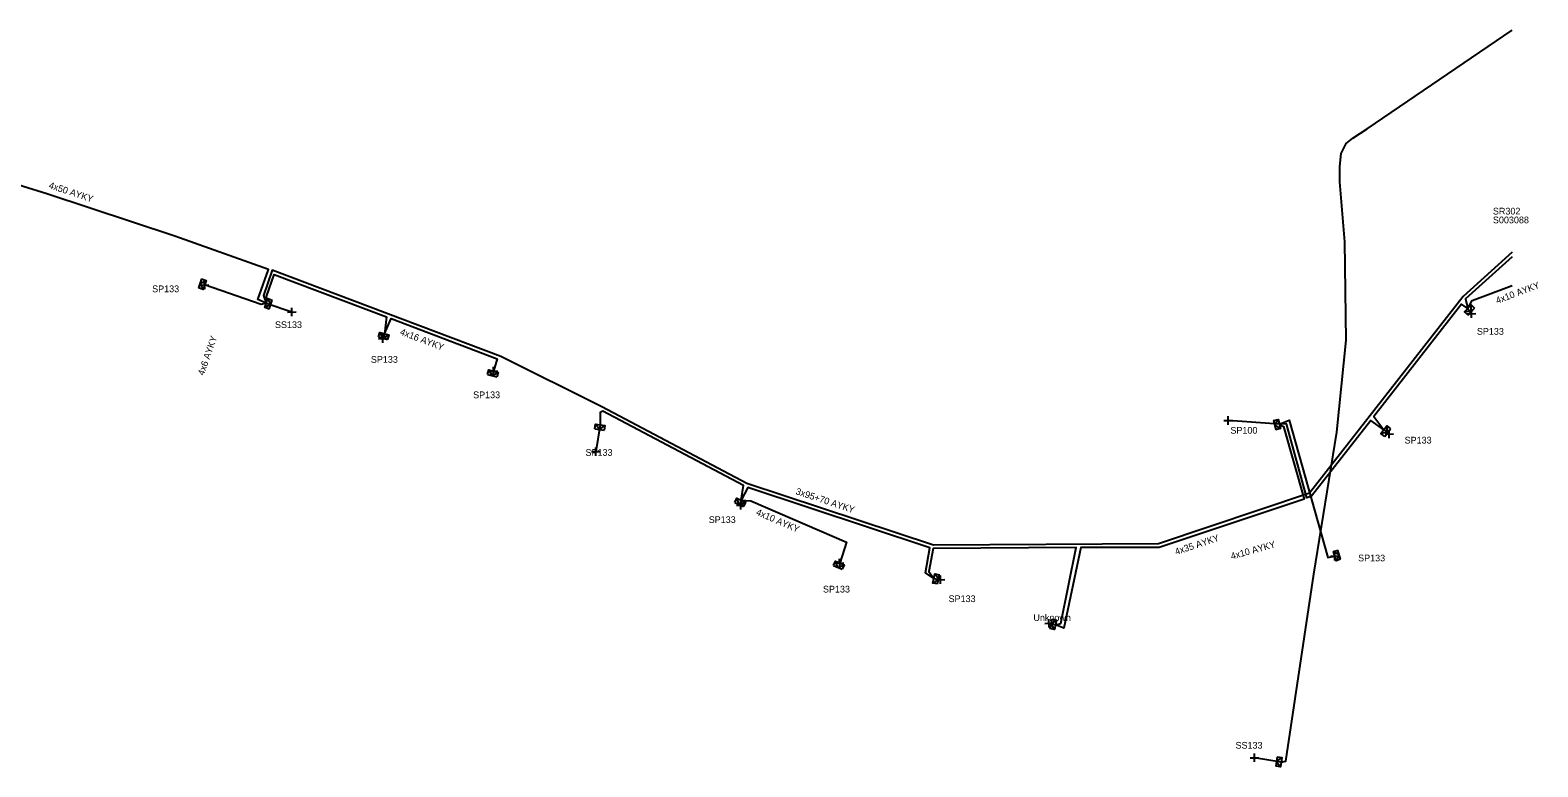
# Model space of a CAD drawing. Extents: x -762931 to -762496, y -1153652 to -1153451.
# Drawn here: x -762719.1 to -762496.2, y -1153574.3 to -1153465.2 of the extents above; entities that cross this region are included whole.
import ezdxf

# ---------------------------------------------------------------- set-up
doc = ezdxf.new("R2010")
doc.units = 0
for name, color, linetype in [('Vrstva 29', 7, 'Continuous'), ('Vrstva 30', 7, 'Continuous'), ('Vrstva 31', 7, 'Continuous'), ('Vrstva 33', 7, 'Continuous'), ('Vrstva 34', 7, 'Continuous'), ('Vrstva 5', 7, 'Continuous'), ('Vrstva 52', 7, 'Continuous'), ('Vrstva 54', 7, 'Continuous'), ('Vrstva 59', 7, 'Continuous'), ('Vrstva 6', 7, 'Continuous')]:
    doc.layers.add(name, color=color, linetype=linetype)

msp = doc.modelspace()

# ---------------------------------------------------------------- linework, layer by layer
at = {"layer": 'Vrstva 31'}
for points in [[(-762693.799, -1153502.055), (-762694.232, -1153503.387)], [(-762693.799, -1153502.055), (-762693.134, -1153502.271), (-762693.566, -1153503.603), (-762694.232, -1153503.387)], [(-762694.016, -1153502.721), (-762693.134, -1153502.271)], [(-762694.016, -1153502.721), (-762693.566, -1153503.603)], [(-762683.806, -1153506.513), (-762684.468, -1153506.285), (-762684.012, -1153504.961), (-762683.351, -1153505.189)], [(-762683.578, -1153505.851), (-762684.012, -1153504.961)], [(-762683.578, -1153505.851), (-762684.468, -1153506.285)], [(-762683.806, -1153506.513), (-762683.351, -1153505.189)], [(-762506.534, -1153507.392), (-762507.038, -1153506.906), (-762506.065, -1153505.899), (-762505.562, -1153506.385)], [(-762506.048, -1153506.889), (-762507.038, -1153506.906)], [(-762506.534, -1153507.392), (-762505.562, -1153506.385)], [(-762506.048, -1153506.889), (-762506.065, -1153505.899)], [(-762667.638, -1153510.63), (-762667.445, -1153509.957), (-762666.1, -1153510.343), (-762666.293, -1153511.015)], [(-762667.638, -1153510.63), (-762666.293, -1153511.015)], [(-762666.965, -1153510.822), (-762667.445, -1153509.957)], [(-762666.965, -1153510.822), (-762666.1, -1153510.343)], [(-762651.499, -1153516.17), (-762651.306, -1153515.497), (-762649.96, -1153515.883), (-762650.153, -1153516.556)], [(-762651.499, -1153516.17), (-762650.153, -1153516.556)], [(-762650.826, -1153516.363), (-762651.306, -1153515.497)], [(-762650.826, -1153516.363), (-762649.96, -1153515.883)], [(-762535.289, -1153523.007), (-762534.61, -1153522.838), (-762534.272, -1153524.196), (-762534.951, -1153524.365)], [(-762535.12, -1153523.686), (-762534.61, -1153522.838)], [(-762635.664, -1153524.232), (-762635.554, -1153523.541), (-762634.172, -1153523.76), (-762634.281, -1153524.451)], [(-762635.664, -1153524.232), (-762634.281, -1153524.451)], [(-762634.972, -1153524.342), (-762635.554, -1153523.541)], [(-762634.972, -1153524.342), (-762634.172, -1153523.76)], [(-762535.289, -1153523.007), (-762534.951, -1153524.365)], [(-762535.12, -1153523.686), (-762534.272, -1153524.196)], [(-762518.851, -1153525.345), (-762519.403, -1153524.914), (-762518.541, -1153523.811), (-762517.989, -1153524.242)], [(-762518.42, -1153524.794), (-762519.403, -1153524.914)], [(-762518.851, -1153525.345), (-762517.989, -1153524.242)], [(-762518.42, -1153524.794), (-762518.541, -1153523.811)], [(-762614.953, -1153535.128), (-762614.657, -1153534.494), (-762613.388, -1153535.085), (-762613.684, -1153535.72)], [(-762614.953, -1153535.128), (-762613.684, -1153535.72)], [(-762614.319, -1153535.424), (-762614.657, -1153534.494)], [(-762614.319, -1153535.424), (-762613.388, -1153535.085)], [(-762525.365, -1153543.548), (-762526.034, -1153543.752), (-762526.443, -1153542.414), (-762525.774, -1153542.209)], [(-762525.569, -1153542.878), (-762526.443, -1153542.414)], [(-762525.569, -1153542.878), (-762526.034, -1153543.752)], [(-762525.365, -1153543.548), (-762525.774, -1153542.209)], [(-762600.361, -1153544.47), (-762600.087, -1153543.825), (-762598.798, -1153544.372), (-762599.072, -1153545.017)], [(-762600.361, -1153544.47), (-762599.072, -1153545.017)], [(-762599.716, -1153544.743), (-762600.087, -1153543.825)], [(-762599.716, -1153544.743), (-762598.798, -1153544.372)], [(-762584.967, -1153547.194), (-762585.654, -1153547.06), (-762585.387, -1153545.686), (-762584.699, -1153545.82)], [(-762584.833, -1153546.507), (-762585.654, -1153547.06)], [(-762584.833, -1153546.507), (-762585.387, -1153545.686)], [(-762584.967, -1153547.194), (-762584.699, -1153545.82)], [(-762568.059, -1153552.407), (-762568.35, -1153553.776)], [(-762568.059, -1153552.407), (-762567.374, -1153552.552), (-762567.665, -1153553.922), (-762568.35, -1153553.776)], [(-762568.204, -1153553.092), (-762567.374, -1153552.552)], [(-762568.204, -1153553.092), (-762567.665, -1153553.922)], [(-762534.741, -1153572.776), (-762534.96, -1153574.159)], [(-762534.741, -1153572.776), (-762534.05, -1153572.886), (-762534.269, -1153574.269), (-762534.96, -1153574.159)], [(-762534.851, -1153573.468), (-762534.05, -1153572.886)], [(-762534.851, -1153573.468), (-762534.269, -1153574.269)]]:
    msp.add_lwpolyline(points, dxfattribs=at)
at = {"layer": 'Vrstva 34'}
for points in [[(-762693.339, -1153503.565), (-762693.361, -1153502.315)], [(-762693.975, -1153502.951), (-762692.725, -1153502.929)], [(-762681.085, -1153506.951), (-762679.835, -1153506.929)], [(-762680.449, -1153507.565), (-762680.471, -1153506.315)], [(-762506.635, -1153507.201), (-762505.385, -1153507.179)], [(-762505.999, -1153507.815), (-762506.021, -1153506.565)], [(-762667.655, -1153510.901), (-762666.405, -1153510.879)], [(-762667.019, -1153511.515), (-762667.041, -1153510.265)], [(-762651.255, -1153515.701), (-762650.005, -1153515.679)], [(-762650.619, -1153516.315), (-762650.641, -1153515.065)], [(-762541.989, -1153523.625), (-762542.011, -1153522.375)], [(-762542.625, -1153523.011), (-762541.375, -1153522.989)], [(-762518.805, -1153525.001), (-762517.555, -1153524.979)], [(-762518.169, -1153525.615), (-762518.191, -1153524.365)], [(-762635.489, -1153528.225), (-762635.511, -1153526.975)], [(-762636.125, -1153527.611), (-762634.875, -1153527.589)], [(-762614.695, -1153535.541), (-762613.445, -1153535.519)], [(-762614.059, -1153536.155), (-762614.081, -1153534.905)], [(-762526.229, -1153543.705), (-762526.251, -1153542.455)], [(-762600.065, -1153544.111), (-762598.815, -1153544.089)], [(-762599.429, -1153544.725), (-762599.451, -1153543.475)], [(-762526.865, -1153543.091), (-762525.615, -1153543.069)], [(-762585.165, -1153546.581), (-762583.915, -1153546.559)], [(-762584.529, -1153547.195), (-762584.551, -1153545.945)], [(-762569.115, -1153553.041), (-762567.865, -1153553.019)], [(-762568.479, -1153553.655), (-762568.501, -1153552.405)], [(-762538.725, -1153572.931), (-762537.475, -1153572.909)], [(-762538.089, -1153573.545), (-762538.111, -1153572.295)]]:
    msp.add_lwpolyline(points, dxfattribs=at)
at = {"layer": 'Vrstva 5'}
for points in [[(-762534.16, -1153573.58), (-762533.46, -1153573.43), (-762529.35, -1153545.73), (-762525.93, -1153524.73), (-762524.53, -1153511.12), (-762524.75, -1153496.55), (-762525.5, -1153487.66), (-762525.5, -1153485.41), (-762525.28, -1153483.48), (-762524.53, -1153481.98), (-762523.57, -1153481.23), (-762521.43, -1153479.83), (-762500, -1153465.22)], [(-762684.24, -1153505.63), (-762685.48, -1153505.11), (-762683.91, -1153500.67), (-762697.74, -1153495.71), (-762716.68, -1153489.45), (-762734.23, -1153484.04), (-762735.08, -1153486.3), (-762734.77, -1153483.77), (-762762.48, -1153477.29), (-762770.33, -1153477.43), (-762771.21, -1153481.02), (-762770.99, -1153477.38), (-762782.7, -1153472.86), (-762785.25, -1153470), (-762790.32, -1153468.44), (-762791.03, -1153470.57), (-762790.01, -1153471.4)], [(-762500, -1153498.1), (-762507.27, -1153504.67), (-762529.98, -1153533.78), (-762552.31, -1153541.28), (-762585.56, -1153541.46), (-762613.17, -1153532.34), (-762634.61, -1153520.99), (-762649.56, -1153513.51), (-762683.37, -1153500.73), (-762684.66, -1153504.51), (-762684.24, -1153505.63)], [(-762500, -1153498.8), (-762506.9, -1153505.01), (-762506.55, -1153506.4), (-762507.51, -1153505.78), (-762520.47, -1153522.43), (-762518.97, -1153524.36), (-762520.92, -1153522.99), (-762529.68, -1153534.2), (-762530.36, -1153534.43), (-762533.36, -1153523.48), (-762534.44, -1153523.52), (-762533.8, -1153523.88), (-762530.78, -1153534.62), (-762552.22, -1153541.78), (-762563.8, -1153541.8), (-762566.32, -1153553.74), (-762567.52, -1153553.24), (-762566.72, -1153553.03), (-762564.46, -1153541.8), (-762585.64, -1153541.96), (-762586.27, -1153545.35), (-762585.52, -1153546.37), (-762586.74, -1153545.57), (-762586.12, -1153541.83), (-762613.03, -1153532.93), (-762614.02, -1153534.79), (-762613.65, -1153532.64), (-762634.47, -1153521.64), (-762634.84, -1153521.8), (-762634.86, -1153523.65)], [(-762684.24, -1153505.63), (-762684.18, -1153504.64), (-762683.07, -1153501.38), (-762666.46, -1153507.67), (-762666.77, -1153510.15)]]:
    msp.add_lwpolyline(points, dxfattribs=at)
at = {"layer": 'Vrstva 52'}
for points in [[(-762684.24, -1153505.63), (-762684.97, -1153505.82), (-762693.35, -1153502.94)], [(-762506.55, -1153506.4), (-762505.93, -1153505.24), (-762500, -1153503)], [(-762666.77, -1153510.15), (-762665.77, -1153507.91), (-762650.08, -1153513.85), (-762650.63, -1153515.7)], [(-762534.44, -1153523.52), (-762532.98, -1153522.93), (-762527.26, -1153543.27), (-762526.24, -1153543.08)], [(-762614.02, -1153534.79), (-762612.6, -1153534.88), (-762598.42, -1153541), (-762599.44, -1153544.1)]]:
    msp.add_lwpolyline(points, dxfattribs=at)
at = {"layer": 'Vrstva 59'}
for points in [[(-762684.24, -1153505.62), (-762680.46, -1153506.94)], [(-762506.55, -1153506.4), (-762506.01, -1153507.19)], [(-762666.77, -1153510.15), (-762667.03, -1153510.89)], [(-762634.86, -1153523.65), (-762635.5, -1153527.6)], [(-762534.44, -1153523.52), (-762542, -1153523)], [(-762518.97, -1153524.36), (-762518.18, -1153524.99)], [(-762614.02, -1153534.79), (-762614.07, -1153535.53)], [(-762585.52, -1153546.37), (-762584.54, -1153546.57)], [(-762567.52, -1153553.24), (-762568.49, -1153553.03)], [(-762534.16, -1153573.58), (-762538.1, -1153572.92)]]:
    msp.add_lwpolyline(points, dxfattribs=at)

# ---------------------------------------------------------------- texts
at = {"layer": 'Vrstva 29'}
msp.add_text('S003088', height=0.9943, dxfattribs=at).set_placement((-762502.85, -1153493.81))
at = {"layer": 'Vrstva 30'}
msp.add_text('SR302', height=0.9943, dxfattribs=at).set_placement((-762502.85, -1153492.51))
at = {"layer": 'Vrstva 33'}
for s, p in [('SP133', (-762701.11, -1153504.01)), ('SS133', (-762682.95, -1153509.32)), ('SP133', (-762505.22, -1153510.31)), ('SP133', (-762668.77, -1153514.46)), ('SP133', (-762653.65, -1153519.7)), ('SP100', (-762541.67, -1153524.95)), ('SP133', (-762637.03, -1153528.23)), ('SP133', (-762515.91, -1153526.41)), ('SP133', (-762618.81, -1153538.17)), ('SP133', (-762522.78, -1153543.85)), ('SP133', (-762601.92, -1153548.46)), ('SP133', (-762583.34, -1153549.88)), ('Unknown', (-762570.8, -1153552.68)), ('SS133', (-762540.91, -1153571.57))]:
    msp.add_text(s, height=0.9943, dxfattribs=at).set_placement(p)
at = {"layer": 'Vrstva 54'}
for s, rotation, p in [('4x10 AYKY', 20.71843, (-762502.21, -1153505.75)), ('4x16 AYKY', 339.25374, (-762664.55, -1153510.26)), ('4x6 AYKY', 71.00738, (-762693.46, -1153516.41)), ('4x10 AYKY', 336.65975, (-762611.91, -1153536.93)), ('4x10 AYKY', 15.7055, (-762541.47, -1153543.59))]:
    msp.add_text(s, height=0.9943, rotation=rotation, dxfattribs=at).set_placement(p)
at = {"layer": 'Vrstva 6'}
for s, height, rotation, p in [('4x50 AYKY', 0.9943, 341.71625, (-762716.48, -1153488.59)), ('3x95+70 AYKY', 0.99429, 341.72114, (-762606.03, -1153533.89)), ('4x35 AYKY', 0.9943, 18.47873, (-762549.69, -1153542.92))]:
    msp.add_text(s, height=height, rotation=rotation, dxfattribs=at).set_placement(p)

doc.saveas('drawing.dxf')
